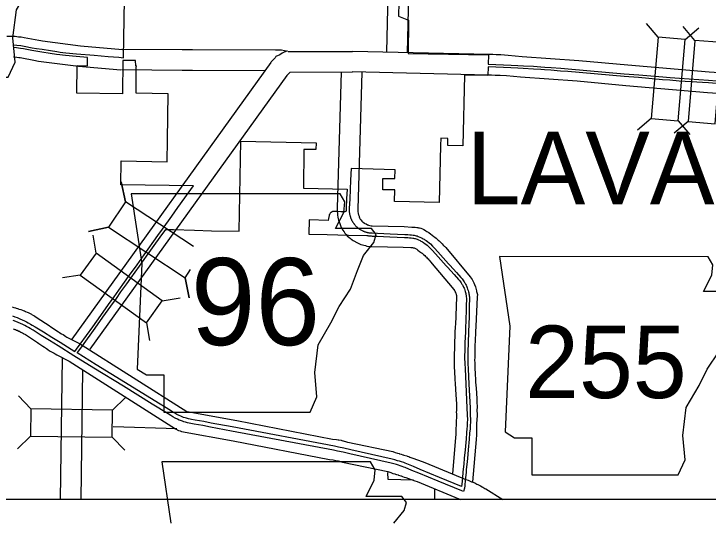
# Model space of a CAD drawing. Extents: x 535214 to 694517, y 381272 to 484355.
# Drawn here: x 556953 to 562013, y 448004 to 451713 of the extents above; entities that cross this region are included whole.
import ezdxf

# ---------------------------------------------------------------- set-up
doc = ezdxf.new("R2010")
doc.units = 0
for name, color, linetype in [('1', 7, 'Continuous'), ('Level 10', 7, 'Continuous'), ('Level 20', 7, 'Continuous'), ('Level 21', 7, 'Continuous'), ('Level 6', 7, 'Continuous'), ('Level 7', 7, 'Continuous')]:
    doc.layers.add(name, color=color, linetype=linetype)

msp = doc.modelspace()

# ---------------------------------------------------------------- linework, layer by layer
at = {"layer": '1'}
msp.add_lwpolyline([(535213.7, 480223.3), (566227, 480223.3), (566227, 448175.2), (535213.7, 448175.2)], close=True, dxfattribs=at)
at = {"layer": 'Level 10'}
for points in [[(559703, 452907), (559668.8, 451437)], [(559852.9, 452904.1), (559818.7, 451429.4)], [(556900.3, 451551.4), (556961.9, 451550.3), (556987.1, 451546.9), (556995.6, 451546.5)], [(556992.3, 451546.6), (557004.8, 451546.4), (557027.3, 451542), (557135.6, 451521.3), (557149.1, 451519.4), (557160.4, 451516.4), (557438.3, 451480.6), (557743.9, 451454.9)], [(558943.6, 451443.8), (558909, 451426.9), (558890.9, 451415.8), (558862.4, 451401.9), (558858.3, 451393.7), (558827.9, 451363.8), (558826.6, 451360), (557373.9, 449343.3)], [(558946.3, 451438.9), (558903, 451448), (558876.8, 451448.2), (558859.5, 451449.4), (558255.5, 451450.9), (558179.4, 451451.1), (557738.3, 451455.2)], [(558952, 451439.5), (559419.8, 451440.2)], [(562958.4, 451213.2), (562639.9, 451247.4), (562020.8, 451289.1), (561427.2, 451339), (561072, 451372.3), (560657.9, 451401.7), (560555.7, 451411.1), (560503.2, 451414.2), (560468, 451415.1), (560443.1, 451416.7), (560416.4, 451418), (559421.6, 451440.2)], [(556950.5, 451400.5), (556973.1, 451397.4), (556987.6, 451396.7)], [(556989.4, 451396.6), (556998.7, 451394.7), (557110.7, 451373.4), (557119.2, 451372.1), (557131.8, 451368.9), (557422.4, 451331.4), (557731.4, 451305.4)], [(558964.6, 451286.5), (558943.4, 451265.6), (557506.4, 449270.6)], [(558783, 451299.6), (558255.1, 451300.9), (558178.5, 451301.1), (557737, 451305.2)], [(558963.2, 451289.5), (559420.1, 451290.2)], [(559339.3, 451290.7), (559309.8, 450298.2), (559309.2, 450290.5), (559309.1, 450273.6), (559310.6, 450262.7), (559311.4, 450255.8), (559312.3, 450246.7), (559313.9, 450232), (559317.1, 450220.3), (559319.4, 450210.7), (559323.2, 450199), (559325, 450194.6), (559325.7, 450192.8), (559327.6, 450186.3), (559330.3, 450178.6), (559333.2, 450170.6), (559339.4, 450157.9), (559344.8, 450148.4), (559349, 450139.7), (559359.1, 450125.7), (559366.1, 450116.7), (559374.1, 450106.7), (559383, 450096.8), (559396.1, 450084.3), (559401.9, 450080.1), (559402.8, 450079.4), (559409.2, 450074.1), (559416.4, 450069.7), (559419.6, 450067.4), (559426.2, 450062.4), (559440.2, 450054.2), (559442.1, 450053.3), (559462.9, 450042.6), (559472.3, 450038.3), (559482.3, 450034.5), (559493.7, 450030.9), (559503.3, 450028.7), (559515.4, 450025.8), (559526.1, 450021.4), (559546.4, 450019.5), (559562, 450019.4), (559791.1, 450014.3), (559846.9, 450010.8), (559854.6, 450010.7), (559858.9, 450010.4), (559862.6, 450010), (559870.5, 450008.7), (559888.9, 449998.6), (559891.9, 449996.7), (559896.5, 449993.1), (559909.6, 449982.2), (559916.8, 449977.6), (559923.4, 449972.7), (559927.7, 449969.4), (559933.9, 449964.3), (559938.4, 449960.4), (559947.1, 449952.1), (559953.7, 449946.9), (559956.6, 449944.2), (559959.4, 449941.3), (559965.4, 449934.7), (559971.5, 449928.5), (559977.9, 449920.9), (559985.1, 449913.6), (559990.8, 449908.1), (560159.5, 449706), (560165.5, 449697.5), (560166.1, 449696.8), (560169.9, 449689.4), (560173, 449682.2), (560173.3, 449681.6), (560177.2, 449666.6), (560178.6, 449664.1), (560179.9, 449649.7), (560170.9, 449449.2), (560169.3, 449437.5), (560168.5, 449417.8), (560167.9, 449406.7), (560167.3, 449394.7)], [(563019.2, 451078.9), (562936.1, 451065.8), (562924.8, 451065.9), (562626.8, 451097.9), (562009.5, 451139.5), (561413.9, 451189.6), (561059.7, 451222.8), (560645.6, 451252.1), (560544.3, 451261.5), (560497, 451264.3), (560461.3, 451265.2), (560434.4, 451267), (560411.1, 451268.1), (559418.3, 451290.2)], [(559489.4, 451288.8), (559459.7, 450290), (559459.2, 450283.8), (559459.2, 450283.7), (559459.5, 450281.5), (559460.6, 450271.4), (559461.5, 450262.4), (559461.7, 450260.1), (559462.4, 450257.7), (559463.9, 450251.3), (559464, 450251), (559465.1, 450248.4), (559468.4, 450239.1), (559470.3, 450232.6), (559471.5, 450229.3), (559472.2, 450227.8), (559477.6, 450218.3), (559478.3, 450216.9), (559479.1, 450215.8), (559483.9, 450209.7), (559488.7, 450203.6), (559490.7, 450201.4), (559491.7, 450200.4), (559496.2, 450196.7), (559499, 450195), (559508.6, 450188.2), (559509.9, 450187.3), (559521.6, 450182.9), (559529.8, 450176.9), (559530.4, 450176.7), (559531.4, 450176.3), (559532.9, 450175.8), (559537.3, 450174.8), (559546.7, 450172.6), (559556.7, 450169.5), (559564.3, 450169.4), (559797.5, 450164.2), (559852.4, 450160.7), (559860.7, 450160.7), (559872.4, 450159.8), (559877.9, 450159.2), (559889.9, 450158.2), (559896.6, 450156.4), (559901.3, 450155.7), (559908.7, 450154.1), (559919.1, 450151.7), (559931.7, 450146.8), (559940.4, 450142.4), (559953.4, 450135.1), (559956.3, 450132.7), (559963.8, 450128.5), (559977.6, 450120.2), (559990.9, 450109.7), (559998.6, 450103.3), (560002.3, 450100.9), (560013.6, 450092.6), (560021.2, 450086.7), (560030.8, 450078.8), (560039.2, 450071.5), (560045.4, 450065.7), (560051.6, 450060.7), (560061.6, 450051.3), (560068.7, 450044.1), (560074.6, 450037.6), (560082.4, 450029.7), (560088.8, 450022.1), (560090.5, 450020.3), (560100.6, 450010.7), (560278.6, 449797.5), (560285.4, 449787.8), (560293.6, 449777.5), (560300.4, 449763.7), (560305.6, 449753.7), (560310.3, 449742.8), (560318.3, 449725), (560325.4, 449695.5), (560326, 449692), (560332.9, 449668.6), (560330.2, 449653.3), (560320.5, 449435.5), (560318.9, 449424.2), (560318.4, 449410.9), (560317.7, 449399), (560317.1, 449387.1)], [(556939, 449578.3), (556952.6, 449575), (556964, 449572), (556969.5, 449569.8), (556978.9, 449567.2), (556987.1, 449563.8), (556989.6, 449563.1), (557002.5, 449559.6), (557015.7, 449554.3), (557020.3, 449552.4), (557029.1, 449549), (557038.4, 449544.9), (557049, 449540), (557056.2, 449536.9), (557065.5, 449532.1), (557070.5, 449529.5), (557080.2, 449524.9), (557087, 449520.8), (557097.4, 449515.5), (557100.5, 449513.6), (557112.6, 449507.1), (557122.2, 449500.1), (557209.4, 449442.7), (557221, 449434.6), (557234.6, 449425.2), (557244.9, 449418.1), (557255.6, 449411.5), (557266.3, 449404.6), (557277.7, 449396.8), (557284.5, 449391.6), (557288.7, 449389), (557300.1, 449382.7), (557310.8, 449376.6), (557322.7, 449369.7), (557332.4, 449363.7), (557339.6, 449359.3), (557430.5, 449312.7), (558212.1, 448817.7), (558214.8, 448816), (558214.8, 448815.9), (558578.5, 448750.7), (559274.6, 448615.9), (559304.9, 448613.5), (559317.2, 448610.5), (559322.4, 448609.5), (559338, 448607.2), (559343.4, 448604.8), (559351.2, 448603)], [(556948.5, 449418.8), (556954.7, 449417.2), (556959.3, 449415.3), (556964.7, 449413.1), (556971.8, 449410.3), (556976.4, 449408.3), (556987.7, 449403), (556992.4, 449401), (556997.1, 449398.6), (557003.9, 449395.1), (557009.2, 449392.6), (557014.3, 449389.6), (557023.8, 449384.7), (557025.6, 449383.6), (557032.4, 449379.9), (557036.7, 449376.8), (557125.2, 449318.5), (557135.4, 449311.4), (557149.6, 449301.6), (557163.1, 449292.4), (557175.3, 449284.8), (557183.4, 449279.6), (557189.8, 449275.2), (557198.9, 449268.2), (557212.6, 449259.6), (557227.1, 449251.7), (557236.2, 449246.5), (557245.1, 449241.3), (557253.4, 449236.2), (557266, 449228.4), (557356, 449182.3), (558131.1, 448691.5), (558139.4, 448686.1), (558143.6, 448683.9), (558153.7, 448678.3), (558163.6, 448674.9), (558174.5, 448670.8), (558551, 448603.3), (559254.3, 448467.1), (559280.9, 448465), (559290.4, 448462.6), (559311.9, 448458.1), (559318.3, 448456.7)], [(560167.3, 449393.5), (560163.9, 449294.2), (560162.6, 449214.6), (560161.4, 449193), (560161.7, 449168.1), (560162.1, 449151.4), (560161.9, 449135.8), (560163.4, 449112.6), (560164.8, 449090), (560166.6, 449070), (560168.2, 449048.3), (560169, 449023.9), (560171.7, 448977.6), (560177.4, 448903.3), (560178.1, 448873.7), (560178.8, 448854.9), (560178.8, 448847.4), (560178.2, 448836.4), (560178.1, 448824.7), (560177.9, 448812.7), (560178.8, 448800.2), (560178.8, 448792.2), (560179.1, 448786.4), (560176.3, 448733.9), (560174.2, 448676.2), (560174, 448652), (560172.4, 448624.5), (560149.6, 448364.2)], [(560317.2, 449388.3), (560313.8, 449290.5), (560312.6, 449209.1), (560311.4, 449189.7), (560311.7, 449170.6), (560312.1, 449152.2), (560312, 449139.9), (560313.1, 449122), (560314.3, 449101.5), (560316.1, 449082.5), (560318.1, 449056.2), (560318.8, 449030.5), (560321.3, 448987.7), (560327.2, 448910.8), (560328, 448878.5), (560328.9, 448857.2), (560328.7, 448842.7), (560328.1, 448831.7), (560328, 448823.4), (560328, 448817.3), (560328.9, 448804.8), (560328.8, 448795.8), (560329.3, 448786.7), (560326.1, 448727.2), (560324.2, 448672.8), (560323.9, 448647), (560322, 448613.6), (560294.9, 448303.4)], [(557304.6, 449206.9), (557289.7, 448175.2)], [(557453.4, 449119.2), (557439.8, 448175.2)], [(559353.6, 448602.4), (559359.4, 448600.9), (559368.9, 448599.1), (559385.3, 448594.1), (559385.8, 448593.9), (559716.2, 448524.1), (559733.1, 448518.7), (559747.9, 448513.8), (559760.2, 448509.6), (559763.9, 448507.9), (559775.3, 448505.1), (559787.4, 448501.2), (559789.5, 448500.5), (559796.3, 448499.5), (559815.9, 448493.3), (559820.2, 448490.8), (559830.7, 448487.7), (559839.6, 448483.4), (559846.4, 448481.3), (559860.9, 448475.7), (559929, 448452.3), (559948.5, 448444.3), (560247.5, 448321.5), (560264, 448316), (560283.7, 448306.1), (560289.2, 448303.9), (560297, 448301.2), (560312.9, 448296), (560328, 448287.5), (560334.7, 448284.1), (560344.7, 448279), (560352.9, 448275), (560365.7, 448268.1), (560371.1, 448264.6), (560378.4, 448260.6), (560386.1, 448256), (560392.7, 448252.6), (560516.4, 448175.2)], [(559315.9, 448457.3), (559326, 448454.6), (559332.5, 448453.4), (559349, 448448.3), (559677.8, 448378.9), (559686.7, 448376.1), (559699.8, 448371.7), (559705.5, 448369.8), (559715.7, 448365.3), (559728.5, 448362.2), (559734.1, 448360.8), (559741, 448358.5), (559754.9, 448354.1), (559755.3, 448354), (559774.5, 448347.9), (559776.4, 448347.3), (559784.4, 448343.5), (559797.4, 448339.4), (559809.8, 448334.7), (559876.1, 448311.9), (559891.4, 448305.6), (560195.3, 448180.7), (560206.6, 448177), (560210.3, 448175.2)]]:
    msp.add_lwpolyline(points, dxfattribs=at)
at = {"layer": 'Level 20'}
for p, q in [((561648.5, 451543.2), (561563.3, 451644)), ((561917.1, 451520.6), (561831.9, 451621.4)), ((561845.8, 451526.6), (561946.7, 451611.8)), ((561598.8, 450951.3), (561498, 450866.1)), ((561867.3, 450928.7), (561766.5, 450843.5)), ((561796.1, 450934.7), (561881.3, 450833.9)), ((557552.7, 449971.3), (557531.5, 450101.6)), ((557436.9, 449810.6), (557306.7, 449789.5)), ((558034.7, 449624.1), (558164.9, 449645.3)), ((557918.9, 449463.5), (557940.1, 449333.2)), ((557077.2, 448835.2), (556985.3, 448929.9)), ((557671.2, 448826.7), (557765.9, 448918.7)), ((557074.4, 448637.3), (556979.7, 448545.3)), ((557668.3, 448628.7), (557760.3, 448534))]:
    msp.add_line(p, q, dxfattribs=at)
for points in [[(561648.5, 451543.2), (561598.8, 450951.3), (561796.1, 450934.7), (561845.8, 451526.6)], [(561917.1, 451520.6), (561867.3, 450928.7), (562064.6, 450912.1), (562114.4, 451504)], [(558034.7, 449624.1), (557552.7, 449971.3), (557436.9, 449810.6), (557918.9, 449463.5)], [(557074.4, 448637.3), (557668.3, 448628.7), (557671.2, 448826.7), (557077.2, 448835.2)]]:
    msp.add_lwpolyline(points, close=True, dxfattribs=at)
msp.add_lwpolyline([(558260.7, 450018), (557765, 450344.8), (557735.3, 450489.8), (557765, 450344.8), (557642.4, 450158.9), (557497.4, 450129.1), (557642.4, 450158.9), (558200.2, 449791), (558230, 449646), (558200.2, 449791), (558239.5, 449850.5)], dxfattribs=at)
at = {"layer": 'Level 21'}
for points in [[(555608.6, 452842.5), (555684.7, 452335), (555650.9, 451565.2), (555718.6, 451522.9), (555845.5, 451522.9), (555845.5, 451252.3), (556911.3, 451252.3), (556962, 451362.2), (556945.1, 451539.9), (556970.5, 451742.9), (557063.5, 451903.6), (557122.8, 452022), (557207.3, 452148.9), (557258.1, 452284.2), (557300.4, 452394.2), (557376.5, 452487.3), (557393.4, 452546.5), (557359.6, 452588.8), (557097.4, 452588.8), (557156.6, 452707.2), (557165.1, 452783.3), (557130, 452841.8)], [(557808.7, 450402.7), (557884.8, 449895.2), (557851, 449125.4), (557918.7, 449083.1), (558045.6, 449083.1), (558045.6, 448812.5), (559111.4, 448812.5), (559162.1, 448922.4), (559145.2, 449100.1), (559170.6, 449303.1), (559263.6, 449463.8), (559322.9, 449582.2), (559407.4, 449709.1), (559458.2, 449844.5), (559500.5, 449954.4), (559576.6, 450047.5), (559593.5, 450106.7), (559559.7, 450149), (559297.5, 450149), (559356.7, 450267.4), (559365.1, 450343.5), (559330.1, 450402)], [(560492.2, 449945.2), (560568.3, 449437.6), (560534.5, 448667.9), (560602.1, 448625.6), (560729, 448625.6), (560729, 448354.9), (561794.8, 448354.9), (561845.6, 448464.9), (561828.7, 448642.5), (561854.1, 448845.5), (561947.1, 449006.2), (562006.3, 449124.7), (562090.9, 449251.6), (562141.7, 449386.9), (562184, 449496.9), (562260.1, 449589.9), (562277, 449649.1), (562243.2, 449691.4), (561980.9, 449691.4), (562040.2, 449809.8), (562048.6, 449886), (562013.5, 449944.4)]]:
    msp.add_lwpolyline(points, close=True, dxfattribs=at)
msp.add_lwpolyline([(559723.4, 448003.6), (559798.6, 448095.6), (559815.6, 448154.8), (559781.7, 448197.1), (559519.5, 448197.1), (559578.7, 448315.5), (559587.2, 448391.7), (559552.1, 448450.1), (558030.7, 448450.9), (558097.8, 448003.6)], dxfattribs=at)
at = {"layer": 'Level 6'}
for points in [[(557752.4, 451394.5), (557761.7, 451962.2), (558422.5, 451951), (558424.3, 452116.9), (559088.9, 452104.5), (559092.2, 452273.4), (559427.3, 452266.9), (559424, 452098.3), (559749.3, 452092.3)], [(559760.4, 451903.2), (559756.7, 451696.2)], [(559756.7, 451696.2), (559828.1, 451667.9), (559828.6, 451655.2), (559826.6, 451424.4), (560411.3, 451414.4), (560410.9, 451347.9)], [(556950.2, 451488.2), (556974, 451485.7), (557003.4, 451482), (557026.7, 451478), (557086.4, 451466.9), (557116.2, 451462.1), (557158.5, 451455.4), (557219.5, 451445.8), (557266.3, 451438.6), (557290.2, 451435.2), (557309.6, 451432.6), (557332, 451430.2), (557408.7, 451423.2), (557538.5, 451412.1), (557639.3, 451404), (557716.5, 451397.5), (557752.4, 451394.5)], [(557839.9, 451372.9), (557774.1, 451374.2), (557747.6, 451375), (557743.5, 451130.7), (557411.1, 451135.1), (557414.6, 451337.4), (557489.3, 451336.1), (557489.9, 451396.2), (557406.9, 451403.3), (557330, 451410.3), (557307.2, 451412.8), (557287.5, 451415.4), (557263.3, 451418.8), (557216.4, 451426), (557155.4, 451435.7), (557113, 451442.3), (557082.9, 451447.2), (557023.1, 451458.4), (557000.5, 451462.2), (556971.7, 451465.8), (556948.2, 451468.3)], [(558262.2, 450460.8), (557732.5, 450468.1), (557735.4, 450642.9), (558068.8, 450634.9), (558071.6, 450795), (558077.4, 451131.6), (557844.7, 451134.7), (557844.7, 451218.7), (557844.7, 451327.9), (557845.3, 451335.4), (557840.6, 451335.4), (557839.9, 451372.9)], [(560409.7, 451327.9), (560408.6, 451264.4), (560237.3, 451267.3), (560225.2, 450751.9), (560115.5, 450753.6), (560116.8, 450806.1), (560064.3, 450807.1), (560063, 450754.6), (560053.3, 450339.7), (559728.1, 450347.7), (559729.5, 450430.8), (559641.3, 450432.5), (559642.4, 450515.2), (559730.8, 450513.4), (559731.9, 450577.4), (559410.6, 450586)], [(562277.6, 451211.7), (562276.3, 451191.7), (562257.5, 451192.9), (562222.7, 451195.2), (562110.4, 451203.6), (562075.2, 451206.2), (562015.1, 451210.5), (561803.4, 451224.5), (561734.2, 451229.7), (561681.4, 451234.2), (561505.6, 451249.1), (561400.4, 451257.9), (560990.7, 451293.1), (560938.1, 451297.2), (560867.7, 451302.7), (560821.6, 451306.3), (560793.1, 451308.5), (560739.9, 451311.4), (560665.8, 451315.7), (560626.2, 451317.8), (560576.1, 451320.4), (560521.5, 451323), (560409.7, 451327.9)], [(560410.9, 451347.9), (560522.4, 451342.9), (560577, 451340.4), (560627.2, 451337.8), (560666.9, 451335.7), (560741, 451331.4), (560794.4, 451328.4), (560823.1, 451326.3), (560869.2, 451322.6), (560939.6, 451317.1), (560992.4, 451313), (561402.1, 451277.8), (561507.3, 451269), (561683.1, 451254.1), (561735.7, 451249.6), (561804.8, 451244.5), (562016.4, 451230.4), (562076.6, 451226.1), (562111.9, 451223.6), (562224.1, 451215.1), (562258.8, 451212.9), (562277.6, 451211.7)], [(558594, 450129.7), (558605.8, 450786), (559155.3, 450773.7), (559154.7, 450725.3), (559066.6, 450726), (559062.9, 450443.6), (559381, 450437.5)], [(559410.6, 450586), (559406.3, 450501.6), (559400.4, 450365.9), (559397.5, 450296.5), (559397.2, 450271.3)], [(557397.7, 449253.8), (557408.9, 449269.7), (557436.3, 449307.1), (557527.6, 449434.2), (557585.3, 449515.6), (557642.4, 449595.3), (557683.1, 449652.8), (557717, 449699.7), (557760, 449757.9), (557788.4, 449799.1), (557850.8, 449886.2), (557902.5, 449958.8), (558002.2, 450097.9), (558035.5, 450144.3), (558104, 450240.8), (558148.8, 450302.9), (558262.2, 450460.8)], [(559381, 450437.5), (559377.9, 450366.8), (559375.1, 450297.2), (559374.8, 450277.7), (559373.9, 450277.1), (559369.5, 450274.4), (559365.1, 450272.3), (559361.9, 450271.1), (559356.9, 450270.4), (559354.1, 450270.1), (559350.6, 450270.2), (559344.4, 450270.5), (559336, 450271.4), (559310, 450273.9), (559293.4, 450274.6), (559285.3, 450274.6), (559282.1, 450274.4), (559278.7, 450274.1), (559276.9, 450273.8), (559274.5, 450273.2), (559272.1, 450272), (559269.4, 450270.4), (559267.2, 450268.8), (559265, 450267.2), (559263.3, 450265.7), (559260.9, 450263.3), (559259.2, 450261.1), (559256.7, 450257.5), (559255, 450254.8), (559253.1, 450251.7), (559251.9, 450248.5), (559250.5, 450243.6), (559246.4, 450222.3), (559244.6, 450209.4), (559103.9, 450212.7), (559102.5, 450108.3), (559236.6, 450105.5), (559391.2, 450101.3), (559524.3, 450099.5)], [(559397.2, 450271.3), (559397.5, 450267.8), (559398.1, 450263.6), (559399.2, 450258), (559400.3, 450253.2), (559400.9, 450250.6), (559402.1, 450246.5), (559403.3, 450242.2), (559404.6, 450237.6), (559405.6, 450234.3), (559406.7, 450230.9), (559407.6, 450228.3), (559408.8, 450225.3), (559410, 450222.1), (559411.4, 450218.8), (559413, 450215.3), (559414.8, 450211.6), (559418.1, 450205.5), (559421.7, 450199.1), (559425, 450193.5), (559427.8, 450189.2), (559430.5, 450185.2), (559432.1, 450183), (559433.6, 450181), (559434.9, 450179.4), (559436.8, 450177.2), (559440, 450173.6), (559443.8, 450169.8), (559448.3, 450165.4), (559452.9, 450161.2), (559457.1, 450157.5), (559459.8, 450155.2), (559462.7, 450152.7), (559465.6, 450150.5), (559468.5, 450148.4), (559472.6, 450145.7), (559476.5, 450143.2), (559481.8, 450140.2), (559486.3, 450137.7), (559491.1, 450135.3), (559495.4, 450133.3), (559499.8, 450131.3), (559502.8, 450130), (559506.6, 450128.4), (559511.4, 450126.7), (559516.3, 450125.1), (559520.2, 450124), (559524.9, 450122.7), (559528.7, 450121.7), (559532, 450120.9), (559536, 450120.2), (559539.8, 450119.5), (559545.2, 450119), (559549.3, 450118.5), (559557.6, 450118), (559564.3, 450117.7)], [(557414.7, 449243.2), (557425.2, 449258), (557452.5, 449295.4), (557543.9, 449422.6), (557601.6, 449503.9), (557658.7, 449583.7), (557699.4, 449641.1), (557733.2, 449687.9), (557776.3, 449746.3), (557804.8, 449787.6), (557867.1, 449874.6), (557918.8, 449947.2), (558018.5, 450086.3), (558059.5, 450143.4)], [(558059.5, 450143.4), (558116.4, 450142.4), (558269.8, 450138.4), (558393.4, 450133.7), (558594, 450129.7)], [(559564.3, 450117.7), (559602.8, 450115.8), (559694.5, 450111.9), (559801.3, 450107), (559825.2, 450105.7), (559838.7, 450104.6), (559852.3, 450103.2), (559864, 450101.8), (559870.6, 450100.7), (559877.2, 450099.4), (559884.4, 450097.7), (559891.9, 450095.3), (559900.8, 450091.9), (559910.7, 450087.5), (559923.3, 450081.9), (559929.7, 450078.7), (559936.7, 450075.1), (559943.2, 450071.6), (559949.4, 450068), (559957.3, 450062.8), (559968.8, 450054.6), (559980.4, 450045.2), (559989.3, 450037.3), (560004.5, 450021.4), (560018.5, 450007), (560043.4, 449979.3), (560121.3, 449892.9), (560130.3, 449882.7), (560178.4, 449829.8), (560211, 449793.1), (560219.8, 449782.6), (560225.9, 449775), (560231.1, 449768.2), (560234.9, 449762.5), (560238.3, 449757.3), (560242.2, 449750.7), (560245.8, 449744.2), (560249.1, 449737.3), (560251.8, 449731.7), (560254.8, 449724.8), (560257.5, 449717.6), (560260.5, 449708.9), (560264, 449698.4), (560266.7, 449689.2), (560268.5, 449681.6), (560270.1, 449673.8), (560271.2, 449667.6), (560272.4, 449660.1), (560273.1, 449652.9), (560273.5, 449642.1), (560273.5, 449627.2), (560272.6, 449597), (560272.4, 449571), (560271.6, 449531.5), (560270.5, 449509), (560266.5, 449396.5), (560263.5, 449317.3), (560261.3, 449251.7), (560260.9, 449228.6), (560260.9, 449208.4), (560262.4, 449167.1), (560263.9, 449127.2)], [(559524.3, 450099.5), (559532.2, 450098), (559536.8, 450097.2), (559542.8, 450096.6), (559547.4, 450096.1), (559556.4, 450095.5), (559563.4, 450095.2), (559601.8, 450093.3), (559693.6, 450089.5), (559800.2, 450084.6), (559823.7, 450083.3), (559836.6, 450082.2), (559849.8, 450080.9), (559860.8, 450079.5), (559866.6, 450078.5), (559872.5, 450077.4), (559878.4, 450076), (559884.5, 450074.1), (559892.2, 450071.1), (559901.5, 450066.9), (559913.7, 450061.5), (559919.6, 450058.6), (559926.2, 450055.2), (559932.1, 450052), (559937.5, 450048.9), (559944.6, 450044.2), (559955.2, 450036.6), (559965.9, 450028.1), (559973.6, 450021.1), (559988.3, 450005.8), (560002, 449991.6), (560026.7, 449964.2), (560104.5, 449878), (560113.5, 449867.7), (560161.7, 449814.7), (560194, 449778.4), (560202.3, 449768.4), (560208.2, 449761.1), (560212.8, 449755), (560216.2, 449750.1), (560219.2, 449745.5), (560222.6, 449739.6), (560225.8, 449733.8), (560228.9, 449727.5), (560231.3, 449722.4), (560233.9, 449716.4), (560236.3, 449710), (560239.2, 449701.6), (560242.6, 449691.6), (560245, 449683.3), (560246.6, 449676.8), (560248, 449669.6), (560249, 449663.9), (560250, 449657.3), (560250.6, 449651.3), (560251, 449641.6), (560251, 449627.5), (560250.2, 449597.4), (560249.9, 449571.3), (560249.1, 449532.3), (560248, 449509.9), (560244, 449397.3), (560241, 449318.1), (560238.8, 449252.2), (560238.4, 449228.8), (560238.4, 449208), (560239.9, 449166.3), (560241.4, 449126.4)], [(556942, 449513.1), (556958.7, 449507.3), (556976.7, 449500.4), (556995.5, 449492.6), (557012.4, 449485.2), (557030.8, 449476.3), (557045.1, 449469.2), (557057.5, 449462.9), (557074.5, 449453.8), (557086.9, 449446.7), (557107.8, 449433.8), (557168.2, 449395.9), (557228.8, 449358.6), (557290.3, 449321.4), (557397.7, 449253.8)], [(557389.8, 449223.3), (557274.5, 449295.8), (557213.2, 449333), (557152.3, 449370.4), (557091.9, 449408.4), (557071.6, 449420.9), (557060.1, 449427.5), (557043.6, 449436.3), (557031.5, 449442.4), (557017.6, 449449.4), (556999.8, 449457.9), (556983.7, 449465.1), (556965.6, 449472.5), (556948.3, 449479.1)], [(560229.9, 448233.3), (560218.3, 448238), (560045, 448309.2), (559903.7, 448366.7), (559853.3, 448387.3), (559804.6, 448407.5), (559794.2, 448411.9), (559784, 448415.9), (559769, 448421.2), (559755.7, 448425.5), (559741.8, 448429.5), (559722.2, 448434.6), (559702.9, 448439.3), (559401.5, 448509.2), (559352, 448520.1), (559312.4, 448528.6), (559283.2, 448534.7), (558537.8, 448674.6), (558385.8, 448703.4), (558330.9, 448713.5), (558267.7, 448725.1), (558241.5, 448730), (558231.1, 448732.2), (558217.9, 448735.2), (558203.5, 448738.9), (558192.5, 448742), (558180.6, 448745.6), (558168.1, 448750.2), (558157.3, 448754.5), (558144.4, 448760.5), (558127.4, 448769.1), (558110.2, 448778.6), (558096.2, 448787), (558077.5, 448798.6), (557960.2, 448871), (557751.5, 449000.1), (557536.2, 449132.1), (557389.8, 449223.3)], [(560216.8, 448271), (560056.4, 448337), (559915, 448394.5), (559864.7, 448415), (559816.2, 448435.2), (559805.4, 448439.7), (559794.4, 448444), (559778.6, 448449.6), (559764.5, 448454.2), (559749.7, 448458.4), (559729.6, 448463.7), (559709.9, 448468.5), (559408.1, 448538.5), (559358.4, 448549.4), (559318.7, 448558), (559289, 448564.2), (558543.3, 448704.1), (558391.3, 448732.9), (558336.3, 448743), (558273.2, 448754.5), (558247.4, 448759.4), (558237.7, 448761.5), (558224.9, 448764.4), (558211.2, 448767.9), (558201, 448770.7), (558190.2, 448774.1), (558178.8, 448778.2), (558169.1, 448782.1), (558157.5, 448787.5), (558141.5, 448795.6), (558125.1, 448804.6), (558111.8, 448812.6), (558093.3, 448824.1), (557976, 448896.5), (557767.2, 449025.6), (557552, 449157.6), (557414.7, 449243.2)], [(560241.4, 449126.4), (560246.3, 449015.5), (560255.3, 448842.5), (560257.4, 448792.2), (560258.5, 448756.3), (560258.1, 448737.5), (560257.2, 448719), (560256.8, 448708.5), (560255.5, 448692.2), (560252.5, 448660.9), (560248.5, 448616.5), (560241.2, 448538.3), (560235.9, 448477.2), (560231.8, 448433.5), (560228.4, 448396.3), (560226.5, 448375.9), (560222.2, 448334.6), (560218.5, 448287.4), (560216.8, 448271)], [(560263.9, 449127.2), (560268.8, 449016.5), (560277.8, 448843.6), (560279.9, 448793.1), (560281, 448756.4), (560280.5, 448736.7), (560279.7, 448718.1), (560279.2, 448707.2), (560277.9, 448690.3), (560274.9, 448658.8), (560270.9, 448614.4), (560263.6, 448536.3), (560258.3, 448475.2), (560254.3, 448431.4), (560250.8, 448394.2), (560248.9, 448373.7), (560244.7, 448332.5), (560240.9, 448285.4), (560239.1, 448267.4), (560238.6, 448263.4), (560238.4, 448262.2), (560237.9, 448259.2), (560229.9, 448233.3)]]:
    msp.add_lwpolyline(points, dxfattribs=at)
at = {"layer": 'Level 7'}
for points in [[(558140.3, 448690.3), (557676.1, 448704.7)], [(559865.7, 448317), (559679.8, 448320.6), (559678.4, 448372.7)], [(560022.1, 448175.2), (560022.2, 448248.6)]]:
    msp.add_lwpolyline(points, dxfattribs=at)

# ---------------------------------------------------------------- texts
at = {"layer": 'Level 21'}
for s, height, p in [('96', 633.6, (558242.3, 449300.6)), ('255', 528, (560679.1, 448914.5))]:
    msp.add_text(s, height=height, dxfattribs=at).set_placement(p)
at = {"layer": 'Level 6'}
msp.add_text('LAVACA', height=528, dxfattribs=at).set_placement((560254.1, 450327))

doc.saveas('drawing.dxf')
